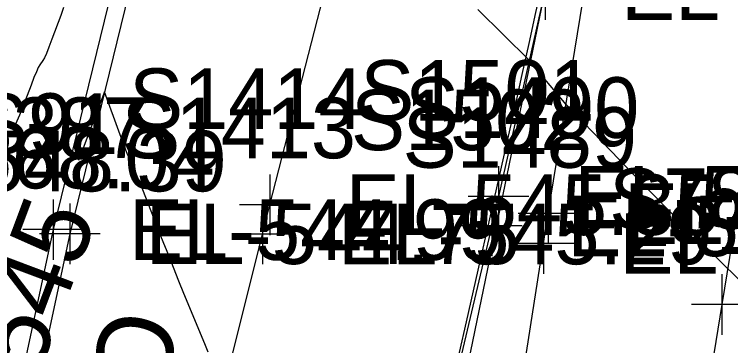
# Model space of a CAD drawing. Extents: x 1724534 to 1727318, y 657156 to 660047.
# Drawn here: x 1725615.54 to 1725662.82, y 659702.31 to 659724.19 of the extents above; entities that cross this region are included whole.
import ezdxf

# ---------------------------------------------------------------- set-up
doc = ezdxf.new("R2010")
doc.units = 0
for name, color, linetype in [('SURVEY - CENTERLINE - Preliminary', 7, 'Continuous'), ('SURVEY - CONTOURS - Index with Text', 7, 'Continuous'), ('SURVEY - CONTOURS - Intermediate with optional Text', 7, 'Continuous'), ('SURVEY - DTM - Breaklines', 7, 'Continuous'), ('SURVEY - DTM - Breaklines - Points - Elevations', 7, 'Continuous'), ('SURVEY - DTM - Breaklines - Points - Locators', 7, 'Continuous'), ('SURVEY - DTM - Breaklines - Points - Numbers', 7, 'Continuous'), ('SURVEY - NON-TRANSPORTATION - Features - Points - Elevations', 7, 'Continuous'), ('SURVEY - TRAFFIC CONTROL - Pavement Marking - Points - Locators', 7, 'Continuous'), ('SURVEY - TRAFFIC CONTROL - Pavement Marking - Points - Numbers', 7, 'Continuous'), ('SURVEY - TRAFFIC CONTROL - Pavement Marking with Text', 7, 'Continuous'), ('SURVEY - TRANSPORTATION - Features', 7, 'Continuous'), ('SURVEY - TRANSPORTATION - Features - Points - Elevations', 7, 'Continuous'), ('SURVEY - TRANSPORTATION - Features - Points - Locators', 7, 'Continuous'), ('SURVEY - TRANSPORTATION - Features - Points - Numbers', 7, 'Continuous'), ('SURVEY - TRANSPORTATION - Features Text', 7, 'Continuous'), ('SURVEY - TRANSPORTATION - Roads', 7, 'Continuous'), ('SURVEY - TRANSPORTATION - Roads - Points - Elevations', 7, 'Continuous'), ('SURVEY - TRANSPORTATION - Roads - Points - Locators', 7, 'Continuous'), ('SURVEY - TRANSPORTATION - Roads - Points - Numbers', 7, 'Continuous')]:
    doc.layers.add(name, color=color, linetype=linetype)

msp = doc.modelspace()

# ---------------------------------------------------------------- linework, layer by layer
at = {"layer": 'SURVEY - CENTERLINE - Preliminary'}
msp.add_line((1725655.279, 659748.62), (1725645.182, 659699.65), dxfattribs=at)
msp.add_arc((1722720.51, 660371.052), 3000, 345.79242, 348.349411, dxfattribs=at)
msp.add_arc((1722720.51, 660371.052), 3000, 345.79242, 348.349411, dxfattribs=at)
msp.add_arc((1722720.51, 660371.052), 3000, 345.79242, 348.349411, dxfattribs=at)
at = {"layer": 'SURVEY - CONTOURS - Index with Text'}
msp.add_lwpolyline([(1725628.33, 659701.888), (1725628.155, 659702.326), (1725627.675, 659703.486), (1725626.841, 659705.495), (1725626.491, 659706.352), (1725626.359, 659706.685), (1725625.778, 659708.162), (1725625.213, 659709.54), (1725624.912, 659710.299), (1725623.86, 659712.992), (1725623.695, 659713.403), (1725623.534, 659713.783), (1725623.341, 659714.215), (1725623.135, 659714.667), (1725623.039, 659714.891), (1725622.907, 659715.226), (1725622.739, 659715.67), (1725622.534, 659716.225), (1725621.492, 659719.069), (1725619.786, 659714.538)], dxfattribs=at)
at = {"layer": 'SURVEY - CONTOURS - Intermediate with optional Text'}
for points in [[(1725618.796, 659724.636), (1725618.599, 659724.112), (1725618.02, 659722.547), (1725617.82, 659722.02), (1725617.655, 659721.611), (1725617.525, 659721.32), (1725617.429, 659721.148), (1725617.219, 659720.847), (1725617.124, 659720.678), (1725616.996, 659720.4), (1725616.835, 659720.011), (1725616.641, 659719.511), (1725616.08, 659718.031), (1725615.884, 659717.528), (1725615.714, 659717.128), (1725615.57, 659716.833), (1725615.454, 659716.64)], [(1725663.42, 659706.616), (1725662.032, 659707.986), (1725659.622, 659710.37), (1725658.722, 659711.266), (1725657.828, 659712.168), (1725656.94, 659713.073), (1725656.058, 659713.984), (1725651.957, 659718.245), (1725649.851, 659720.757), (1725649.644, 659721.008), (1725649.526, 659721.159), (1725646.121, 659724.515)]]:
    msp.add_lwpolyline(points, dxfattribs=at)
at = {"layer": 'SURVEY - DTM - Breaklines'}
msp.add_lwpolyline([(1725639.982, 659805.546), (1725635.79, 659784.47), (1725629.921, 659758.494), (1725625.443, 659739.387), (1725624.054, 659734.362), (1725618.103, 659709.974), (1725612.874, 659685.67), (1725607.844, 659661.097), (1725602.477, 659636.589), (1725597.046, 659612.281)], dxfattribs=at)
at = {"layer": 'SURVEY - DTM - Breaklines - Points - Locators'}
for p, q in [((1725618.103, 659711.974), (1725618.103, 659707.974)), ((1725620.103, 659709.974), (1725616.103, 659709.974))]:
    msp.add_line(p, q, dxfattribs=at)
at = {"layer": 'SURVEY - TRAFFIC CONTROL - Pavement Marking - Points - Locators'}
for p, q in [((1725662.242, 659707.025), (1725662.242, 659703.025)), ((1725664.242, 659705.025), (1725660.242, 659705.025))]:
    msp.add_line(p, q, dxfattribs=at)
at = {"layer": 'SURVEY - TRAFFIC CONTROL - Pavement Marking with Text'}
msp.add_lwpolyline([(1725677.077, 659796.306), (1725674.763, 659781.986), (1725662.242, 659705.025), (1725649.129, 659624.102), (1725636.683, 659547.114), (1725636.368, 659545.139), (1725624.177, 659468.103), (1725623.248, 659462.175), (1725617.375, 659424.632), (1725617.069, 659422.656), (1725605.507, 659345.515), (1725605.215, 659343.536), (1725602.951, 659328.104)], dxfattribs=at)
at = {"layer": 'SURVEY - TRANSPORTATION - Features'}
msp.add_lwpolyline([(1725641.101, 659805.349), (1725636.902, 659784.236), (1725631.028, 659758.231), (1725626.544, 659739.104), (1725625.155, 659734.079), (1725619.206, 659709.701), (1725613.974, 659685.384), (1725608.945, 659660.816), (1725603.581, 659636.317), (1725598.147, 659611.998)], dxfattribs=at)
at = {"layer": 'SURVEY - TRANSPORTATION - Features - Points - Locators'}
for p, q in [((1725619.206, 659711.701), (1725619.206, 659707.701)), ((1725621.206, 659709.701), (1725617.206, 659709.701))]:
    msp.add_line(p, q, dxfattribs=at)
at = {"layer": 'SURVEY - TRANSPORTATION - Roads'}
for points in [[(1725603.37, 659597.283), (1725609.346, 659620.521), (1725610.838, 659626.331), (1725616.118, 659647.682), (1725616.609, 659649.621), (1725622.545, 659672.869), (1725623.043, 659674.805), (1725627.074, 659690.284), (1725627.572, 659692.221), (1725631.909, 659709.685), (1725632.405, 659711.621), (1725638.875, 659736.793), (1725639.344, 659738.736), (1725642.879, 659754.334), (1725646.579, 659769.894), (1725647.02, 659771.844), (1725650.31, 659787.495), (1725650.689, 659789.457), (1725652.957, 659801.236), (1725653.303, 659803.205)], [(1725632.661, 659598.515), (1725636.547, 659622.193), (1725636.864, 659624.167), (1725641.571, 659653.789), (1725641.894, 659655.762), (1725646.455, 659683.38), (1725646.769, 659685.355), (1725650.47, 659709.06), (1725650.781, 659711.035), (1725658.503, 659758.392), (1725658.822, 659760.366), (1725662.184, 659782.1)], [(1725661.882, 659780.645), (1725658.752, 659764.961), (1725658.346, 659763.003), (1725656.668, 659755.185), (1725656.257, 659753.229), (1725651.004, 659727.775), (1725650.578, 659725.822), (1725647.499, 659712.17), (1725647.046, 659710.223), (1725637.399, 659669.36), (1725636.917, 659667.42), (1725624.67, 659618.957), (1725609.021, 659556.912)]]:
    msp.add_lwpolyline(points, dxfattribs=at)
at = {"layer": 'SURVEY - TRANSPORTATION - Roads - Points - Locators'}
for p, q in [((1725650.578, 659727.822), (1725650.578, 659723.822)), ((1725647.499, 659714.17), (1725647.499, 659710.17)), ((1725632.405, 659713.621), (1725632.405, 659709.621)), ((1725650.781, 659713.035), (1725650.781, 659709.035)), ((1725649.499, 659712.17), (1725645.499, 659712.17)), ((1725647.046, 659712.223), (1725647.046, 659708.223)), ((1725634.405, 659711.621), (1725630.405, 659711.621)), ((1725631.909, 659711.685), (1725631.909, 659707.685)), ((1725652.781, 659711.035), (1725648.781, 659711.035)), ((1725650.47, 659711.06), (1725650.47, 659707.06)), ((1725649.046, 659710.223), (1725645.046, 659710.223)), ((1725633.909, 659709.685), (1725629.909, 659709.685)), ((1725652.47, 659709.06), (1725648.47, 659709.06))]:
    msp.add_line(p, q, dxfattribs=at)

# ---------------------------------------------------------------- texts
at = {"layer": 'SURVEY - CONTOURS - Index with Text'}
msp.add_text('545', height=5, rotation=69.3885, dxfattribs=at).set_placement((1725617.117, 659700.339))
at = {"layer": 'SURVEY - DTM - Breaklines - Points - Elevations'}
for s, p in [('EL-568.04', (1725604.084, 659712.698)), ('EL-544.99', (1725623.103, 659707.974))]:
    msp.add_text(s, height=4, dxfattribs=at).set_placement(p)
at = {"layer": 'SURVEY - DTM - Breaklines - Points - Numbers'}
msp.add_text('S91', height=4, dxfattribs=at).set_placement((1725612.876, 659714.974))
at = {"layer": 'SURVEY - NON-TRANSPORTATION - Features - Points - Elevations'}
msp.add_text('EL-548.39', height=4, dxfattribs=at).set_placement((1725604.872, 659712.501))
at = {"layer": 'SURVEY - TRAFFIC CONTROL - Pavement Marking - Points - Numbers'}
msp.add_text('S786', height=4, dxfattribs=at).set_placement((1725654.796, 659710.025))
at = {"layer": 'SURVEY - TRANSPORTATION - Features - Points - Elevations'}
msp.add_text('EL-544.75', height=4, dxfattribs=at).set_placement((1725624.206, 659707.701))
at = {"layer": 'SURVEY - TRANSPORTATION - Features - Points - Numbers'}
msp.add_text('S387', height=4, dxfattribs=at).set_placement((1725611.87, 659714.701))
at = {"layer": 'SURVEY - TRANSPORTATION - Features Text'}
msp.add_text('CONC.', height=5, rotation=256.6327, dxfattribs=at).set_placement((1725621.668, 659705.002))
at = {"layer": 'SURVEY - TRANSPORTATION - Roads - Points - Elevations'}
for s, p in [('EL-546.14', (1725655.578, 659723.822)), ('EL-545.73', (1725652.499, 659710.17)), ('EL-545.35', (1725637.405, 659709.621)), ('EL-545.79', (1725655.781, 659709.035)), ('EL-545.67', (1725652.046, 659708.223)), ('EL-545.29', (1725636.909, 659707.685)), ('EL-545.74', (1725655.47, 659707.06))]:
    msp.add_text(s, height=4, dxfattribs=at).set_placement(p)
at = {"layer": 'SURVEY - TRANSPORTATION - Roads - Points - Numbers'}
for s, p in [('S1501', (1725638.369, 659717.17)), ('S1414', (1725623.117, 659716.621)), ('S1490', (1725641.32, 659716.035)), ('S1502', (1725637.758, 659715.223)), ('S1413', (1725622.621, 659714.685)), ('S1489', (1725641.167, 659714.06))]:
    msp.add_text(s, height=4, dxfattribs=at).set_placement(p)

doc.saveas('drawing.dxf')
